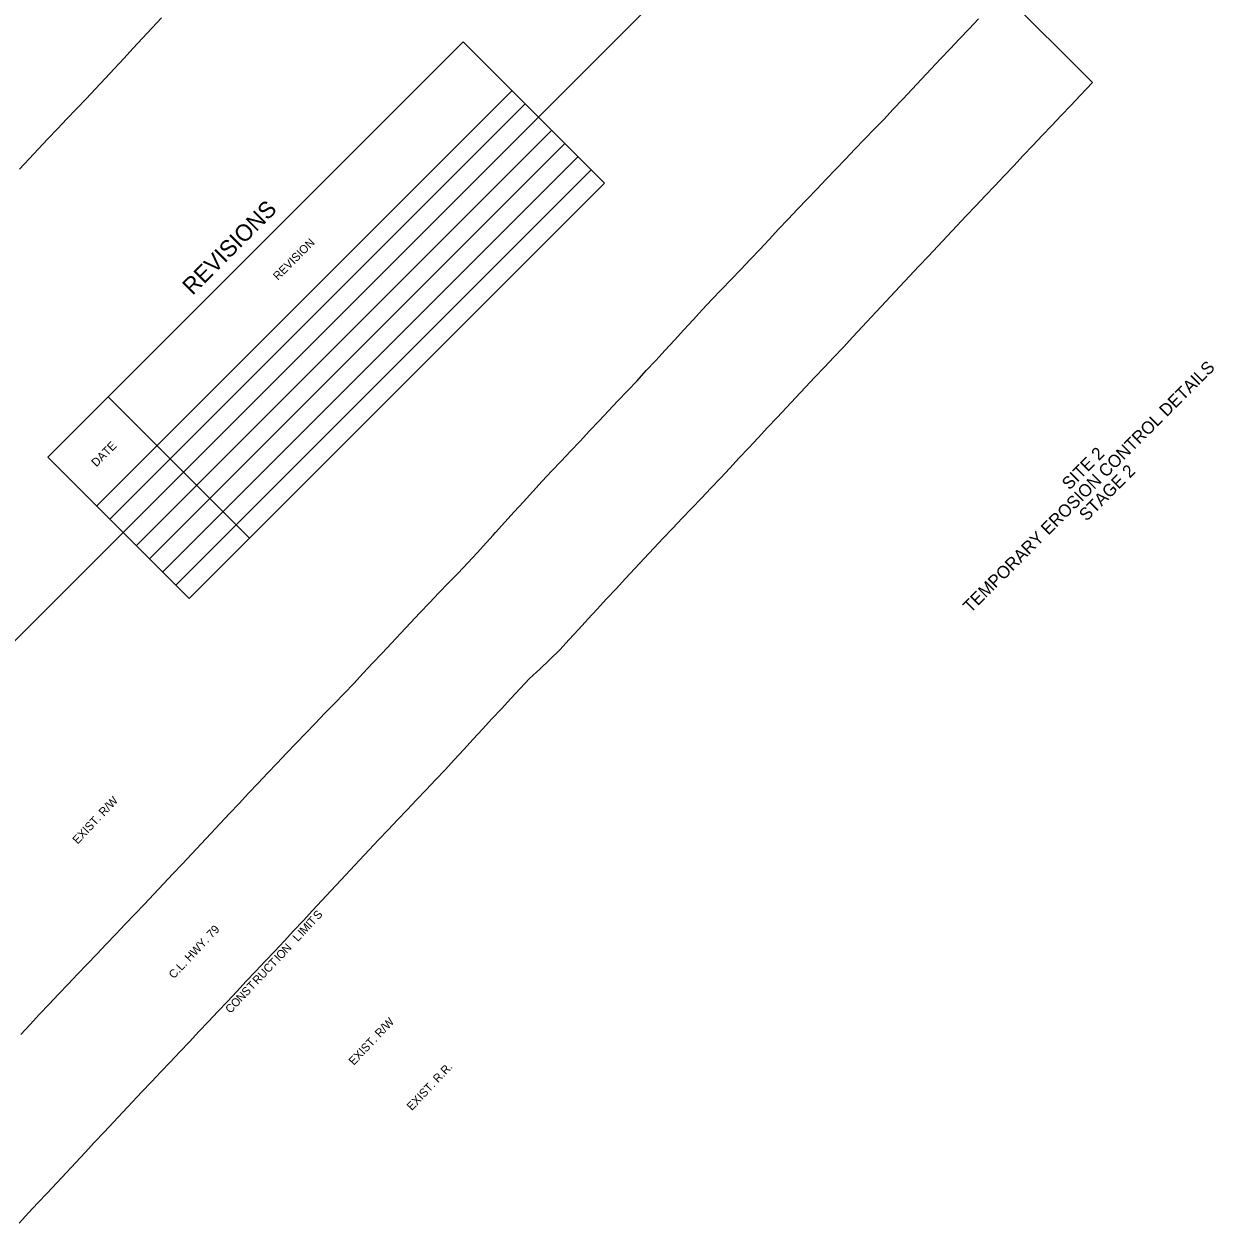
# Model space of a CAD drawing. Extents: x 1388120 to 1389841, y 1944102 to 1945760.
# Drawn here: x 1388980 to 1389841, y 1944440 to 1945307 of the extents above; entities that cross this region are included whole.
import ezdxf

# ---------------------------------------------------------------- set-up
doc = ezdxf.new("R2010")
doc.units = 0
for name, color, linetype in [('1', 7, 'Continuous'), ('60', 7, 'Continuous'), ('Default', 7, 'Continuous'), ('R_Draft', 7, 'Continuous'), ('R_NO PLOT', 7, 'Continuous')]:
    doc.layers.add(name, color=color, linetype=linetype)

msp = doc.modelspace()

# ---------------------------------------------------------------- linework, layer by layer
at = {"layer": '1'}
for p, q in [((1389352.45, 1945239.6), (1389565.28, 1945452.44)), ((1388849.57, 1944736.72), (1389051.93, 1944939.08))]:
    msp.add_line(p, q, dxfattribs=at)
at = {"layer": 'Default'}
for p, q in [((1388997.48, 1944993.53), (1389298, 1945294.05)), ((1389298, 1945294.05), (1389400.18, 1945191.87)), ((1389032.83, 1944958.17), (1389333.35, 1945258.69)), ((1389042.38, 1944948.63), (1389342.9, 1945249.15)), ((1389051.93, 1944939.08), (1389352.45, 1945239.6)), ((1389061.47, 1944929.54), (1389361.99, 1945230.06)), ((1389061.47, 1944929.54), (1389361.99, 1945230.06)), ((1389071.02, 1944919.99), (1389371.54, 1945220.51)), ((1389080.56, 1944910.44), (1389381.08, 1945210.96)), ((1389090.11, 1944900.9), (1389390.63, 1945201.42)), ((1389099.66, 1944891.35), (1389400.18, 1945191.87)), ((1389041.19, 1945037.24), (1389143.36, 1944935.06)), ((1388997.48, 1944993.53), (1389099.66, 1944891.35))]:
    msp.add_line(p, q, dxfattribs=at)
at = {"layer": 'R_NO PLOT'}
for points in [[(1389688.38, 1945329.34), (1389753.12, 1945264.6)], [(1388977.07, 1945201.97), (1388983.9, 1945209.28), (1388990.74, 1945216.57), (1388997.58, 1945223.86), (1389004.47, 1945231.11), (1389011.36, 1945238.36), (1389018.25, 1945245.61), (1389025.14, 1945252.86), (1389032.03, 1945260.1), (1389038.89, 1945267.38), (1389045.7, 1945274.7), (1389052.5, 1945282.04), (1389059.28, 1945289.38), (1389066.04, 1945296.75), (1389072.89, 1945304.04), (1389079.66, 1945311.4)], [(1388977.92, 1944575.97), (1388984.75, 1944583.27), (1388991.59, 1944590.57), (1388998.43, 1944597.86), (1389005.28, 1944605.15), (1389012.16, 1944612.41), (1389019.06, 1944619.63), (1389025.98, 1944626.86), (1389032.89, 1944634.09), (1389039.79, 1944641.32), (1389046.68, 1944648.57), (1389053.57, 1944655.82), (1389060.46, 1944663.07), (1389067.34, 1944670.33), (1389074.23, 1944677.58), (1389081.09, 1944684.85), (1389087.97, 1944692.11), (1389094.84, 1944699.38), (1389101.66, 1944706.68), (1389108.49, 1944713.99), (1389115.33, 1944721.29), (1389122.17, 1944728.58), (1389129.02, 1944735.87), (1389135.86, 1944743.16), (1389142.71, 1944750.45), (1389149.55, 1944757.74), (1389156.39, 1944765.03), (1389163.3, 1944772.26), (1389170.24, 1944779.46), (1389177.17, 1944786.68), (1389184.1, 1944793.88), (1389191.03, 1944801.1), (1389197.97, 1944808.3), (1389204.9, 1944815.5), (1389211.83, 1944822.72), (1389218.75, 1944829.93), (1389225.6, 1944837.22), (1389232.43, 1944844.52), (1389239.28, 1944851.81), (1389246.12, 1944859.11), (1389252.97, 1944866.39), (1389259.82, 1944873.68), (1389266.69, 1944880.95), (1389273.54, 1944888.23), (1389280.39, 1944895.51), (1389287.28, 1944902.76), (1389294.42, 1944909.78), (1389301.29, 1944917.04), (1389308.03, 1944924.43), (1389314.78, 1944931.81), (1389319.61, 1944937.13), (1389321.44, 1944939.13), (1389328.17, 1944946.53), (1389334.89, 1944953.94), (1389341.62, 1944961.33), (1389348.34, 1944968.74), (1389355.07, 1944976.14), (1389361.91, 1944983.43), (1389368.76, 1944990.72), (1389375.62, 1944997.99), (1389382.49, 1945005.26), (1389389.33, 1945012.55), (1389396.24, 1945019.79), (1389403.07, 1945027.09), (1389409.93, 1945034.36), (1389416.84, 1945041.59), (1389423.7, 1945048.87), (1389430.43, 1945056.27), (1389437.29, 1945063.54), (1389444.01, 1945070.95), (1389450.86, 1945078.24), (1389457.59, 1945085.63), (1389464.4, 1945092.96), (1389471.16, 1945100.33), (1389477.93, 1945107.69), (1389484.85, 1945114.91), (1389491.78, 1945122.12), (1389498.69, 1945129.35), (1389505.62, 1945136.56), (1389512.46, 1945143.85), (1389519.33, 1945151.12), (1389526.17, 1945158.42), (1389533.02, 1945165.7), (1389539.88, 1945172.97), (1389546.77, 1945180.22), (1389553.72, 1945187.42), (1389560.57, 1945194.7), (1389567.55, 1945201.87), (1389574.41, 1945209.14), (1389581.38, 1945216.31), (1389588.28, 1945223.55), (1389595.23, 1945230.74), (1389602.17, 1945237.94), (1389609.02, 1945245.23), (1389615.88, 1945252.5), (1389622.73, 1945259.79), (1389629.59, 1945267.06), (1389636.43, 1945274.36), (1389643.3, 1945281.62), (1389650.15, 1945288.92), (1389657, 1945296.2), (1389663.86, 1945303.48), (1389670.73, 1945310.74)], [(1389753.12, 1945264.6), (1389744.31, 1945255.28), (1389737.43, 1945248.02), (1389730.56, 1945240.76), (1389723.7, 1945233.48), (1389716.84, 1945226.2), (1389709.96, 1945218.95), (1389703.09, 1945211.68), (1389696.21, 1945204.42), (1389689.34, 1945197.16), (1389682.46, 1945189.9), (1389675.59, 1945182.63), (1389668.72, 1945175.36), (1389661.88, 1945168.07), (1389655, 1945160.81), (1389648.14, 1945153.54), (1389641.3, 1945146.25), (1389634.44, 1945138.97), (1389627.6, 1945131.67), (1389620.76, 1945124.38), (1389613.92, 1945117.08), (1389607.08, 1945109.79), (1389600.23, 1945102.5), (1389593.41, 1945095.19), (1389586.6, 1945087.86), (1389579.77, 1945080.56), (1389572.97, 1945073.22), (1389566.1, 1945065.96), (1389559.24, 1945058.68), (1389552.37, 1945051.41), (1389545.51, 1945044.14), (1389538.67, 1945036.85), (1389531.83, 1945029.55), (1389525, 1945022.25), (1389518.17, 1945014.94), (1389511.33, 1945007.65), (1389504.5, 1945000.35), (1389497.67, 1944993.04), (1389490.84, 1944985.74), (1389484, 1944978.44), (1389477.16, 1944971.15), (1389470.26, 1944963.91), (1389463.36, 1944956.67), (1389456.48, 1944949.42), (1389449.58, 1944942.18), (1389442.72, 1944934.89), (1389435.82, 1944927.66), (1389428.98, 1944920.37), (1389422.09, 1944913.12), (1389415.28, 1944905.8), (1389408.51, 1944898.43), (1389401.72, 1944891.09), (1389394.95, 1944883.73), (1389388.17, 1944876.38), (1389386.2, 1944874.27), (1389381.33, 1944868.98), (1389374.55, 1944861.63), (1389367.76, 1944854.29), (1389360.6, 1944847.29), (1389353.42, 1944840.32), (1389346, 1944833.57), (1389339.18, 1944826.26), (1389332.39, 1944818.92), (1389325.58, 1944811.59), (1389318.79, 1944804.26), (1389311.99, 1944796.92), (1389305.25, 1944789.54), (1389298.45, 1944782.2), (1389291.71, 1944774.81), (1389284.92, 1944767.47), (1389278.04, 1944760.21), (1389271.16, 1944752.95), (1389264.28, 1944745.7), (1389257.39, 1944738.45), (1389250.51, 1944731.19), (1389243.62, 1944723.95), (1389236.74, 1944716.69), (1389229.85, 1944709.44), (1389222.97, 1944702.18), (1389216.15, 1944694.87), (1389209.35, 1944687.53), (1389202.55, 1944680.2), (1389195.75, 1944672.87), (1389188.94, 1944665.55), (1389182.15, 1944658.21), (1389175.3, 1944650.92), (1389168.52, 1944643.57), (1389161.68, 1944636.27), (1389154.82, 1944629), (1389147.97, 1944621.72), (1389141.1, 1944614.44), (1389134.25, 1944607.16), (1389127.4, 1944599.87), (1389120.55, 1944592.59), (1389113.7, 1944585.31), (1389106.84, 1944578.03), (1389099.97, 1944570.76), (1389093.08, 1944563.52), (1389086.19, 1944556.27), (1389079.3, 1944549.02), (1389072.43, 1944541.75), (1389065.57, 1944534.48), (1389058.73, 1944527.18), (1389051.87, 1944519.91), (1389045.03, 1944512.61), (1389038.19, 1944505.31), (1389031.38, 1944497.99), (1389024.56, 1944490.68), (1389017.74, 1944483.36), (1389010.93, 1944476.04), (1389004.09, 1944468.75), (1388997.23, 1944461.47), (1388990.37, 1944454.19), (1388983.52, 1944446.9), (1388976.68, 1944439.62)]]:
    msp.add_lwpolyline(points, dxfattribs=at)

# ---------------------------------------------------------------- texts
at = {"layer": '60'}
for s, p in [('TEMPORARY EROSION CONTROL DETAILS', (1389665.04, 1944880.41)), ('SITE 2', (1389736.47, 1944969.34)), ('STAGE 2', (1389748.9, 1944946.78))]:
    msp.add_text(s, height=9, rotation=45, dxfattribs=at).set_placement(p)
at = {"layer": 'Default'}
for s, height, p in [('REVISIONS', 12, (1389102.13, 1945110.2)), ('REVISION', 6, (1389163.99, 1945121.15)), ('DATE', 6, (1389032.58, 1944986.2))]:
    msp.add_text(s, height=height, rotation=45, dxfattribs=at).set_placement(p)
at = {"layer": 'R_Draft'}
for s, rotation, p in [('EXIST. R/W', 46.66069, (1389019.07, 1944713.28)), ('S', 47.06386, (1389193.1, 1944658.56)), ('M', 46.7454, (1389183.35, 1944648.1)), ('I', 47.23056, (1389187.79, 1944652.81)), ('T', 47.23056, (1389189.14, 1944654.27)), ('C.L. HWY. 79', 46.73601, (1389088.64, 1944615.89)), ('L', 47.3219, (1389178.37, 1944642.75)), ('I', 46.7454, (1389181.99, 1944646.65)), ('N', 46.86104, (1389170.39, 1944634.16)), ('T', 46.65685, (1389160.99, 1944624.17)), ('I', 46.65685, (1389165.01, 1944628.43)), ('O', 46.86104, (1389166.39, 1944629.89)), ('U', 46.76692, (1389153.16, 1944615.85)), ('C', 46.76692, (1389157.11, 1944620.05)), ('T', 46.66505, (1389145.24, 1944607.46)), ('R', 46.66505, (1389149.26, 1944611.72)), ('N', 46.76554, (1389137.48, 1944599.21)), ('S', 46.73819, (1389141.36, 1944603.34)), ('C', 46.71911, (1389129.58, 1944590.81)), ('O', 46.76554, (1389133.47, 1944594.94)), ('EXIST. R/W', 46.66069, (1389218.84, 1944553.28)), ('EXIST. R.R.', 46.66069, (1389260.86, 1944520.52))]:
    msp.add_text(s, height=6, rotation=rotation, dxfattribs=at).set_placement(p)

doc.saveas('drawing.dxf')
